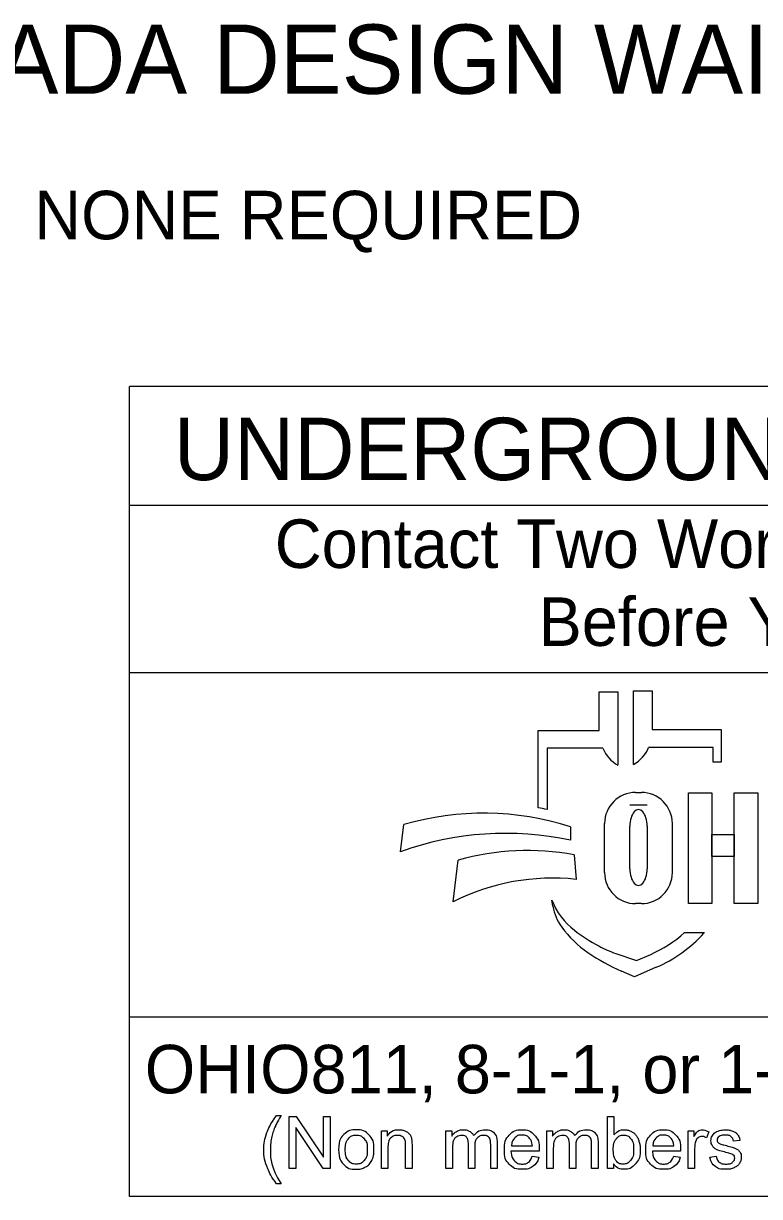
# Model space of a CAD drawing. Extents: x -12 to 34, y 0 to 22.
# Drawn here: x 2.072 to 4.196, y 2.143 to 5.529 of the extents above; entities that cross this region are included whole.
import ezdxf

# ---------------------------------------------------------------- set-up
doc = ezdxf.new("R2010")
doc.units = 0
doc.layers.add('GM_X_Adjacent_County', color=7, linetype='Continuous')
doc.layers.add('GM_X_Township', color=7, linetype='Continuous')

msp = doc.modelspace()

# ---------------------------------------------------------------- linework, layer by layer
at = {"layer": 'GM_X_Adjacent_County'}
for p, q in [((3.7335, 3.4883), (3.7335, 3.5998)), ((3.7335, 3.5998), (3.7872, 3.5998)), ((3.7872, 3.5998), (3.7872, 3.3877)), ((3.8329, 3.39), (3.8329, 3.6021)), ((3.8329, 3.6021), (3.8865, 3.6021)), ((3.8865, 3.6021), (3.8865, 3.4906)), ((3.5576, 3.2644), (3.5576, 3.4883)), ((3.5576, 3.4883), (3.7335, 3.4883)), ((3.8865, 3.4906), (4.0857, 3.4906)), ((4.0857, 3.4906), (4.0857, 3.3968)), ((3.5828, 3.4369), (3.5828, 3.26)), ((3.7439, 3.4369), (3.5828, 3.4369)), ((4.0625, 3.4392), (3.8761, 3.4392)), ((4.0625, 3.3968), (4.0625, 3.4392)), ((4.0857, 3.3968), (4.0625, 3.3968)), ((3.8385, 3.3091), (3.8551, 3.3091)), ((3.8718, 3.2721), (3.822, 3.2721)), ((3.7491, 3.0776), (3.7491, 3.2196)), ((3.9445, 3.2196), (3.9445, 3.0776)), ((3.1602, 3.1381), (3.1696, 3.2162)), ((3.6509, 3.2097), (3.6509, 3.1709)), ((3.822, 3.089), (3.822, 3.2114)), ((3.8718, 3.2114), (3.8718, 3.089)), ((3.6608, 3.1291), (3.6671, 3.0582)), ((3.312, 2.9936), (3.3267, 3.1137)), ((3.5997, 2.9807), (3.5967, 2.9986)), ((3.8551, 2.9882), (3.8385, 2.9882)), ((3.98, 2.9048), (4.0375, 2.9048)), ((3.7816, 2.8444), (3.841, 2.8239)), ((3.841, 2.8239), (3.8821, 2.8417)), ((3.835, 2.7769), (3.7976, 2.7934)), ((3.8983, 2.8044), (3.835, 2.7769))]:
    msp.add_line(p, q, dxfattribs=at)
for points in [[(3.991, 3.3081), (4.0589, 3.3081), (4.0589, 2.9881), (3.991, 2.9881)], [(4.1231, 3.3081), (4.1911, 3.3081), (4.1911, 2.9881), (4.1231, 2.9881)], [(4.0589, 3.1882), (4.1231, 3.1882), (4.1231, 3.1242), (4.0589, 3.1242)]]:
    msp.add_lwpolyline(points, close=True, dxfattribs=at)
for points in [[(2.8021, 2.3766), (2.8153, 2.3766)], [(2.8389, 2.2239), (2.8389, 2.3741), (2.8592, 2.3741), (2.9382, 2.2561), (2.9382, 2.3741), (2.9572, 2.3741), (2.9572, 2.2239), (2.9369, 2.2239), (2.8579, 2.3419), (2.8579, 2.2239), (2.8389, 2.2239)], [(3.7743, 2.2239), (3.7573, 2.2239), (3.7573, 2.3741), (3.7757, 2.3741), (3.7757, 2.3206)], [(3.1048, 2.2239), (3.1048, 2.3328), (3.1214, 2.3328), (3.1214, 2.3173)], [(3.2912, 2.2239), (3.2912, 2.3328), (3.3077, 2.3328), (3.3077, 2.3174)], [(3.5826, 2.2239), (3.5826, 2.3328), (3.5991, 2.3328), (3.5991, 2.3174)], [(3.9904, 2.2239), (3.9904, 2.3328), (4.007, 2.3328), (4.007, 2.3163)], [(4.0495, 2.3293), (4.043, 2.3122)], [(4.1394, 2.3046), (4.1213, 2.3022)], [(3.1233, 2.2833), (3.1233, 2.2239), (3.1048, 2.2239)], [(3.1932, 2.2908), (3.1932, 2.2239), (3.1748, 2.2239), (3.1748, 2.2901)], [(3.3097, 2.2803), (3.3097, 2.2239), (3.2912, 2.2239)], [(3.3743, 2.2871), (3.3743, 2.2239), (3.3559, 2.2239), (3.3559, 2.2946)], [(3.4388, 2.2986), (3.4388, 2.2239), (3.4203, 2.2239), (3.4203, 2.2924)], [(3.56, 2.2736), (3.4788, 2.2736)], [(3.4799, 2.2887), (3.5406, 2.2887)], [(3.601, 2.2803), (3.601, 2.2239), (3.5826, 2.2239)], [(3.6657, 2.2871), (3.6657, 2.2239), (3.6473, 2.2239), (3.6473, 2.2946)], [(3.7301, 2.2986), (3.7301, 2.2239), (3.7117, 2.2239), (3.7117, 2.2924)], [(3.968, 2.2736), (3.8868, 2.2736)], [(3.8879, 2.2887), (3.9486, 2.2887)], [(4.0088, 2.2809), (4.0088, 2.2239), (3.9904, 2.2239)], [(3.5404, 2.2591), (3.5595, 2.2567)], [(3.7743, 2.2375), (3.7743, 2.2239)], [(3.9484, 2.2591), (3.9675, 2.2567)], [(4.053, 2.2564), (4.0712, 2.2593)], [(2.8153, 2.1798), (2.8021, 2.1798)]]:
    msp.add_lwpolyline(points, dxfattribs=at)
for centre, radius, start, end in [((3.8353, 3.4736), 0.0985, 201.9296, 240.7469), ((3.7847, 3.476), 0.0985, 299.2531, 338.0704), ((3.8385, 3.2196), 0.0895, 90, 180), ((3.8551, 3.2196), 0.0895, 0, 90), ((3.4295, 2.4554), 0.8191, 79.2074, 81.0007), ((3.3997, 2.4302), 0.8191, 72.1402, 106.3144), ((3.4628, 2.2991), 0.8919, 77.8238, 109.8274), ((3.5267, 2.4094), 0.7322, 79.44, 105.8467), ((3.5987, 2.4262), 0.6357, 83.8248, 116.8021), ((3.8385, 3.0776), 0.0895, 180, 270), ((3.8551, 3.0776), 0.0895, 270, 0), ((3.7841, 3.0707), 0.2008, 201.0457, 232.5314), ((3.741, 3.0048), 0.1433, 189.6817, 216.0884), ((3.8747, 3.1022), 0.3088, 216.0884, 235.7167), ((3.9766, 3.3219), 0.5173, 232.5314, 241.794), ((3.7387, 3.1722), 0.3602, 293.4582, 312.0712), ((3.7387, 3.1722), 0.401, 293.4582, 317.8286), ((4.0412, 3.3465), 0.6044, 235.7167, 246.2325), ((3.8914, 3.1631), 0.3371, 241.794, 250.9821)]:
    msp.add_arc(centre, radius, start, end, dxfattribs=at)
for centre, start_param, end_param in [((3.8469, 3.2114), 4.712389, 7.853982), ((3.8469, 3.089), 1.570796, 4.712389)]:
    msp.add_ellipse(centre, major_axis=(0, 0.0484), ratio=0.514403, start_param=start_param, end_param=end_param, dxfattribs=at)
for points in [[(2.8021, 2.1798), (2.7869, 2.199), (2.7763, 2.2248), (2.7657, 2.2506), (2.7657, 2.2783), (2.7657, 2.3026), (2.7736, 2.325), (2.7829, 2.3509), (2.8021, 2.3766)], [(2.8153, 2.3766), (2.8029, 2.3553), (2.7989, 2.3462), (2.7927, 2.332), (2.7891, 2.3167), (2.7847, 2.2975), (2.7847, 2.2782), (2.7847, 2.2289), (2.8153, 2.1798)], [(2.9814, 2.2783), (2.9814, 2.3085), (2.9981, 2.3231), (3.0122, 2.3352), (3.0323, 2.3352), (3.0547, 2.3352), (3.069, 2.3205), (3.0832, 2.3058), (3.0832, 2.2799), (3.0832, 2.2589), (3.0769, 2.2469), (3.0706, 2.2348), (3.0586, 2.2282), (3.0466, 2.2215), (3.0323, 2.2215), (3.0095, 2.2215), (2.9954, 2.2362), (2.9814, 2.2508), (2.9814, 2.2783)], [(3.0003, 2.2783), (3.0003, 2.2574), (3.0094, 2.247), (3.0185, 2.2366), (3.0323, 2.2366), (3.046, 2.2366), (3.0551, 2.2471), (3.0642, 2.2575), (3.0642, 2.279), (3.0642, 2.2991), (3.0551, 2.3095), (3.0459, 2.3199), (3.0323, 2.3199), (3.0185, 2.3199), (3.0094, 2.3096), (3.0003, 2.2992), (3.0003, 2.2783)], [(3.1214, 2.3173), (3.1334, 2.3352), (3.156, 2.3352), (3.1659, 2.3352), (3.1741, 2.3316), (3.1823, 2.3281), (3.1864, 2.3224), (3.1905, 2.3166), (3.1922, 2.3087), (3.1932, 2.3036), (3.1932, 2.2908)], [(3.1748, 2.2901), (3.1748, 2.3013), (3.1726, 2.3069), (3.1705, 2.3125), (3.165, 2.3158), (3.1595, 2.3191), (3.1521, 2.3191), (3.1404, 2.3191), (3.1318, 2.3117), (3.1233, 2.3042), (3.1233, 2.2833)], [(3.3077, 2.3174), (3.3128, 2.3254), (3.3214, 2.3303), (3.3299, 2.3352), (3.3407, 2.3352), (3.3528, 2.3352), (3.3606, 2.3301), (3.3683, 2.3251), (3.3715, 2.3161), (3.3844, 2.3352), (3.4051, 2.3352), (3.4213, 2.3352), (3.43, 2.3262), (3.4388, 2.3172), (3.4388, 2.2986)], [(3.3559, 2.2946), (3.3559, 2.3069), (3.3514, 2.313), (3.3469, 2.3191), (3.3366, 2.3191), (3.3288, 2.3191), (3.3222, 2.315), (3.3156, 2.311), (3.3126, 2.3031), (3.3097, 2.2952), (3.3097, 2.2803)], [(3.4203, 2.2924), (3.4203, 2.3035), (3.4185, 2.3083), (3.4168, 2.3132), (3.412, 2.3162), (3.4073, 2.3191), (3.401, 2.3191), (3.3895, 2.3191), (3.3819, 2.3115), (3.3743, 2.3039), (3.3743, 2.2871)], [(3.5595, 2.2567), (3.555, 2.24), (3.5428, 2.2307), (3.5306, 2.2215), (3.5117, 2.2215), (3.4878, 2.2215), (3.4738, 2.2362), (3.4598, 2.2509), (3.4598, 2.2774), (3.4598, 2.3049), (3.474, 2.32), (3.4881, 2.3352), (3.5106, 2.3352), (3.5324, 2.3352), (3.5463, 2.3203), (3.5601, 2.3055), (3.5601, 2.2785), (3.5601, 2.2769), (3.56, 2.2736)], [(3.5406, 2.2887), (3.5394, 2.3025), (3.5337, 2.3094), (3.5249, 2.3201), (3.5108, 2.3201), (3.4981, 2.3201), (3.4894, 2.3115), (3.4808, 2.303), (3.4799, 2.2887)], [(3.5991, 2.3174), (3.6042, 2.3254), (3.6127, 2.3303), (3.6212, 2.3352), (3.6321, 2.3352), (3.6442, 2.3352), (3.6519, 2.3301), (3.6597, 2.3251), (3.6628, 2.3161), (3.6758, 2.3352), (3.6965, 2.3352), (3.7127, 2.3352), (3.7214, 2.3262), (3.7301, 2.3172), (3.7301, 2.2986)], [(3.6473, 2.2946), (3.6473, 2.3069), (3.6428, 2.313), (3.6383, 2.3191), (3.628, 2.3191), (3.6202, 2.3191), (3.6136, 2.315), (3.607, 2.311), (3.604, 2.3031), (3.601, 2.2952), (3.601, 2.2803)], [(3.7117, 2.2924), (3.7117, 2.3035), (3.7099, 2.3083), (3.7081, 2.3132), (3.7034, 2.3162), (3.6987, 2.3191), (3.6923, 2.3191), (3.6809, 2.3191), (3.6733, 2.3115), (3.6657, 2.3039), (3.6657, 2.2871)], [(3.7741, 2.2792), (3.7741, 2.2596), (3.7794, 2.2509), (3.7881, 2.2366), (3.8029, 2.2366), (3.815, 2.2366), (3.8238, 2.2471), (3.8326, 2.2576), (3.8326, 2.2784), (3.8326, 2.2998), (3.8241, 2.3099), (3.8157, 2.3201), (3.8038, 2.3201), (3.7917, 2.3201), (3.7829, 2.3096), (3.7741, 2.299), (3.7741, 2.2792)], [(3.7757, 2.3206), (3.7874, 2.3352), (3.8055, 2.3352), (3.8155, 2.3352), (3.8245, 2.3311), (3.8335, 2.3271), (3.8392, 2.3198), (3.845, 2.3124), (3.8483, 2.3021), (3.8516, 2.2918), (3.8516, 2.28), (3.8516, 2.252), (3.8378, 2.2368), (3.8239, 2.2215), (3.8046, 2.2215), (3.7853, 2.2215), (3.7743, 2.2375)], [(3.9675, 2.2567), (3.963, 2.24), (3.9508, 2.2307), (3.9386, 2.2215), (3.9196, 2.2215), (3.8958, 2.2215), (3.8818, 2.2362), (3.8678, 2.2509), (3.8678, 2.2774), (3.8678, 2.3049), (3.882, 2.32), (3.8961, 2.3352), (3.9186, 2.3352), (3.9404, 2.3352), (3.9543, 2.3203), (3.9681, 2.3055), (3.9681, 2.2785), (3.9681, 2.2769), (3.968, 2.2736)], [(3.9486, 2.2887), (3.9474, 2.3025), (3.9417, 2.3094), (3.9328, 2.3201), (3.9188, 2.3201), (3.9061, 2.3201), (3.8974, 2.3115), (3.8888, 2.303), (3.8879, 2.2887)], [(4.007, 2.3163), (4.0133, 2.3278), (4.0187, 2.3315), (4.0241, 2.3352), (4.0305, 2.3352), (4.0398, 2.3352), (4.0495, 2.3293)], [(4.043, 2.3122), (4.0363, 2.3162), (4.0295, 2.3162), (4.0235, 2.3162), (4.0187, 2.3125), (4.0139, 2.3089), (4.0119, 2.3024), (4.0088, 2.2926), (4.0088, 2.2809)], [(4.1213, 2.3022), (4.1201, 2.3106), (4.1142, 2.3153), (4.1083, 2.3201), (4.0975, 2.3201), (4.0848, 2.3201), (4.0794, 2.3159), (4.0739, 2.3116), (4.0739, 2.306), (4.0739, 2.3024), (4.0762, 2.2995), (4.0785, 2.2966), (4.0833, 2.2946), (4.086, 2.2936), (4.0996, 2.2899), (4.1192, 2.2847), (4.1269, 2.2813), (4.1347, 2.278), (4.1391, 2.2717), (4.1435, 2.2653), (4.1435, 2.2559), (4.1435, 2.2467), (4.1381, 2.2386), (4.1327, 2.2304), (4.1226, 2.226), (4.1124, 2.2215), (4.0996, 2.2215), (4.0784, 2.2215), (4.0672, 2.2303), (4.0561, 2.2391), (4.053, 2.2564)], [(4.0712, 2.2593), (4.0727, 2.2483), (4.0798, 2.2425), (4.0868, 2.2366), (4.0995, 2.2366), (4.1122, 2.2366), (4.1184, 2.2418), (4.1245, 2.247), (4.1245, 2.254), (4.1245, 2.2602), (4.1191, 2.2638), (4.1153, 2.2663), (4.1002, 2.2701), (4.0799, 2.2752), (4.072, 2.2789), (4.0642, 2.2827), (4.0601, 2.2893), (4.0561, 2.2959), (4.0561, 2.3038), (4.0561, 2.3111), (4.0594, 2.3173), (4.0628, 2.3235), (4.0685, 2.3276), (4.0728, 2.3308), (4.0803, 2.333), (4.0877, 2.3352), (4.0962, 2.3352), (4.109, 2.3352), (4.1187, 2.3315), (4.1284, 2.3278), (4.133, 2.3215), (4.1377, 2.3152), (4.1394, 2.3046)], [(3.4788, 2.2736), (3.4799, 2.2557), (3.489, 2.2462), (3.4981, 2.2366), (3.5117, 2.2366), (3.5219, 2.2366), (3.5291, 2.242), (3.5362, 2.2473), (3.5404, 2.2591)], [(3.8868, 2.2736), (3.8879, 2.2557), (3.897, 2.2462), (3.9061, 2.2366), (3.9197, 2.2366), (3.9299, 2.2366), (3.937, 2.242), (3.9442, 2.2473), (3.9484, 2.2591)]]:
    msp.add_open_spline(points, degree=3, dxfattribs=at)
at = {"layer": 'GM_X_Township'}
for p, q in [((2.3775, 2.1428), (2.3775, 4.4803)), ((6.6275, 4.4803), (2.3775, 4.4803)), ((2.3775, 4.1387), (6.6275, 4.1387)), ((2.3775, 3.6553), (6.6275, 3.6553)), ((6.6275, 2.6607), (2.3775, 2.6607)), ((6.6275, 2.1428), (2.3775, 2.1428))]:
    msp.add_line(p, q, dxfattribs=at)

# ---------------------------------------------------------------- texts
at = {"layer": 'GM_X_Adjacent_County'}
for s, height, p in [('ADA DESIGN WAIVERS', 0.2, (1.9944, 5.3256)), ('NONE REQUIRED                          ', 0.14, (2.103, 4.9056)), ('UNDERGROUND UTILITIES', 0.18, (2.5057, 4.2106)), ('Contact Two Working Days', 0.14, (2.7972, 3.9571)), ('Before You Dig', 0.14, (3.5583, 3.7321)), ('OHIO811, 8-1-1, or 1-800-362-2764', 0.14, (2.422, 2.4406))]:
    msp.add_text(s, height=height, dxfattribs=at).set_placement(p)

doc.saveas('drawing.dxf')
